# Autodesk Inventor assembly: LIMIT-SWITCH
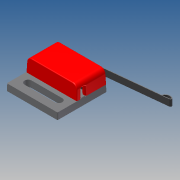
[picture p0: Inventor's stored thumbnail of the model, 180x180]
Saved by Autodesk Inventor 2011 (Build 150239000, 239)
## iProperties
Created: 2008-05
Part Number: LIMIT-SWITCH
Document SubType Name: Assembly
Designer: Phillip Dollan
Author: Phillip Dollan
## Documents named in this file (4)
- C:\Data Folder\VEX 2011\Inventor Datasets\Unit 2\LIMIT-SWITCH.iam
- C:\Data Folder\VEX 2011\Inventor Datasets\Unit 2\LIMIT-SWITCH-MICROSWITCH.ipt
- C:\Data Folder\VEX 2011\Inventor Datasets\Unit 2\LIMIT-SWITCH-BOTTOM.ipt
- C:\Data Folder\VEX 2011\Inventor Datasets\Unit 2\LIMIT-SWITCH-TOP.ipt
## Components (3 placed, 3 different names)
1. LIMIT-SWITCH-MICROSWITCH:1 — Mate:1, Mate:2, Mate:3
2. LIMIT-SWITCH-BOTTOM:1 — Mate:1, Mate:2, Mate:3, Insert:1, Insert:2
3. LIMIT-SWITCH-TOP:1 — Insert:1, Insert:2
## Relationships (5: Mate 3, Insert 2)
- Mate:1: LIMIT-SWITCH-MICROSWITCH:1 ↔ LIMIT-SWITCH-BOTTOM:1
- Mate:2: LIMIT-SWITCH-MICROSWITCH:1 ↔ LIMIT-SWITCH-BOTTOM:1
- Mate:3: LIMIT-SWITCH-MICROSWITCH:1 ↔ LIMIT-SWITCH-BOTTOM:1
- Insert:1: LIMIT-SWITCH-BOTTOM:1 ↔ LIMIT-SWITCH-TOP:1
- Insert:2: LIMIT-SWITCH-BOTTOM:1 ↔ LIMIT-SWITCH-TOP:1
